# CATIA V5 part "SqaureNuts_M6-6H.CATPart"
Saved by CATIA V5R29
Part number: SquareNuts_M6-6H
Bounding box of the stored display mesh (mm): x -7 to 7, y -7 to 7, z -3 to 3
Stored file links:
  C:\Users\Administrator\Desktop\프로젝트\Boxfold\Guide\SqaureNuts_M6-6H.CATPart
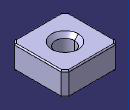
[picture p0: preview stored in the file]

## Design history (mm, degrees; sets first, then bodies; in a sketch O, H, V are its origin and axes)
Body1 (main body)
  Sketch1 on xy-plane, origin (0, 0, 0), H (1, 0, 0), V (0, 1, 0)
    line L1 (7, 7) -> (7, -7)
    line L2 (7, -7) -> (-7, -7)
    line L3 (-7, -7) -> (-7, 7)
    line L4 (-7, 7) -> (7, 7)
    length L3 = 14
    length L4 = 14
    vertical: L1 V, L3 V
    horizontal: L2 H, L4 H
    equidistance: L1 L3 O, L2 L4 O
  Pad1: profile Sketch1, direction (0, 0, 1), length 3, mirrored extent
  Sketch2 on end face of Pad1, origin (0.3753, 1.5089, 3), H (1, 0, 0), V (0, 1, 0)
    point P1 (-0.3753, -1.5089)
    reference projected line E1 (6.6247, -8.5089) -> (6.6247, 5.4911) from edge [face of Pad1 from Sketch1.L1 | end face of Pad1]
    reference projected line E2 (6.6247, 5.4911) -> (-7.3753, 5.4911) from edge [face of Pad1 from Sketch1.L4 | end face of Pad1]
    distance P1 E1 = 7
    distance E2 P1 = 7
  Hole1: placed by Sketch2, at (0, 0, 3) direction (0, 0, -1), diameter 4.917, through (limit type 3), threaded "M6", thread diameter 6, thread depth 6, pitch 1
  Chamfer1: length 1, angle 45, on face of Hole1; edge [face of Pad1 from Sketch1.L4 | face of Pad1 from Sketch1.L1]; edge [face of Pad1 from Sketch1.L3 | face of Pad1 from Sketch1.L4]; edge [face of Pad1 from Sketch1.L1 | face of Pad1 from Sketch1.L2]; edge [face of Pad1 from Sketch1.L2 | face of Pad1 from Sketch1.L3]
  Fillet1: radius 0.3, on edge [face of Pad1 from Sketch1.L3 | end face of Pad1]; edge [end face of Pad1 | face of Chamfer1] (x4); edge [face of Pad1 from Sketch1.L2 | end face of Pad1]; edge [face of Pad1 from Sketch1.L1 | end face of Pad1]; edge [face of Pad1 from Sketch1.L4 | end face of Pad1]; edge [start face of Pad1 | face of Pad1 from Sketch1.L3]; edge [start face of Pad1 | face of Chamfer1] (x4); edge [start face of Pad1 | face of Pad1 from Sketch1.L2]; edge [start face of Pad1 | face of Pad1 from Sketch1.L1]; edge [start face of Pad1 | face of Pad1 from Sketch1.L4]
